// Mitsubishi GX Works2 project: FX3G_COM2_RD3A主机   PLC: FX3G

PROGRAM MAIN
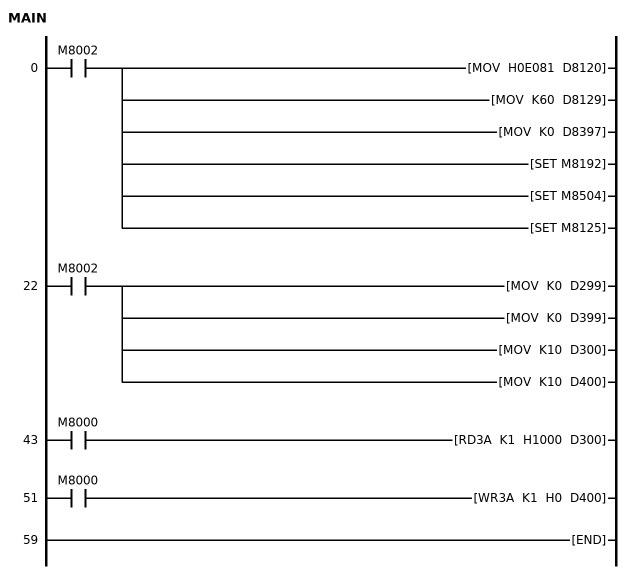
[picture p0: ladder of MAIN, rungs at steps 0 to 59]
0     LD      M8002
      MOV     H0E081 D8120
        [note] 通讯设定9600 8 N 1
      MOV     K60 D8129
        [note] RD3A通讯超时设定
      MOV     K0 D8397
        [note] ADPRW串口2切换
      SET     M8192
        [note] 485模式
      SET     M8504
        [note] RD3A开启
      SET     M8125
        [note] 启用modbus功能
22    LD      M8002
      MOV     K0 D299
        [note] RD3A串口2切换
      MOV     K0 D399
      MOV     K10 D300
        [note] 读取个数
      MOV     K10 D400
43    LD      M8000
      RD3A    K1 H1000 D300
        [note] 读取03功能码
51    LD      M8000
      WR3A    K1 H0 D400
        [note] 写入10功能码
59    END
END_PROGRAM

// device comments not shown above
D200  ; 写入数量，1个
D211  ; 转速
M2  ; 反转
M3  ; 停止
